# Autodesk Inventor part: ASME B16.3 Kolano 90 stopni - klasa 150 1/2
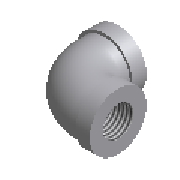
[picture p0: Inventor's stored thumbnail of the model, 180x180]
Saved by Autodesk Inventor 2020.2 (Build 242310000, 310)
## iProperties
Manager: www.cadconsulting.pl
Company: Fabian Stasiak CAD Consulting
NAME: PIPING: ASME B16.3 90 Deg Elbow - Class 150
DATA: <meta><inlinegroups number="0" deflen="0"></inlinegroups><connections number="2"></connections><angles><a>1.57079632679489</a></angles></meta>
IsCustomPart: 0
Created: 2014-02
Part Number: ASME B16.3 Kolano 90 stopni - klasa 150 1/2
Material: Żelazo, ciągliwe
Description: Kolano
Document SubType Name: Modeling
Standard: ASME B16.3
Designer: F.Stasiak
Standard Revision: 1988
Standards Organization: ANSI
Language: pl-PL
Size Designation: 1/2
Categories: <MemberInstance><Categories><Category DisplayName="Rury cienko- i grubościenne" InternalName="4347fa0f-2144-441d-94cd-e3e15c92b736" Mnemonic="TUBEANDPIPE"><Cate
Density: 7.15 g/cm^3
Appearance: Częściowo polerowana
Catalog Web Link: www.expertbooks.pl
Author: F.Stasiak
Subject: Zbiór ćwiczeń. Autodesk Inventor 2020. Kurs Professional
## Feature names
1. Revolution1
2. Sweep1
3. Revolution2
## Parameters: MD = 18.32077 mm, A = 28.448 mm, B = 10.922 mm, G = 2.54 mm, F1 = 22.86 mm, d0 = 18.32077 mm, d1 = 27.94 mm, d2 = 30.48 mm, d3 = 6.35 mm, d4 = 10.922 mm, d5 = 0.3124 mm, d16 = 90 deg, d6 = 22.86 mm, d7 = 27.94 mm, d8 = 90 deg, d9 = 28.448 mm, d10 = 17.526 mm, d11 = 0, d12 = 0.3124 mm, d13 = 10.922 mm, d14 = 6.35 mm, d15 = 18.32077 mm, d17 = 27.94 mm, d18 = 30.48 mm, d51 = 90 deg, P = 1.8143 mm, d58 = 10.922 mm, d59 = 0, d60 = 25.4 mm, d61 = 0, H = 30.48 mm, E1 = 6.35 mm, d63 = 0, Size_Designation = 5 mm
